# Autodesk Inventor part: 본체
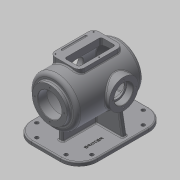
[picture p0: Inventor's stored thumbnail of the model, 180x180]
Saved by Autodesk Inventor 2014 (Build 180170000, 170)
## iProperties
Created: 2016-02
Part Number: 본체
Material: Aluminum 6061
Document SubType Name: Modeling
Designer: mduedu
Density: 2.71 g/cm^3
Appearance: Aluminum - Flat
Author: mduedu
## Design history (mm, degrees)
sketch "스케치2"
  geometry: L1 (0, 100)-(0, -100); L2 (65, -75.993)-(65, 100); L3 (65, 100)-(0, 100); A1 r 100 centre (0, 0) between (0, -100) and (65, -75.993); 2 further points
  constraints: 6 end point, 2 midpoint, 2 point on circle, 1 centre point, 1 coincident, 1 horizontal, 1 parallel, 1 vertical
  dimensions: "d3" = 200 distance of L1.start L1.end; "d5" = 130 diameter of L2 L1; "d6" = 100 radius of A1
revolve "회전1" sketch "스케치2" stored, may be unused: angle "d7" = 90 deg
sketch "스케치3"
  geometry: C1 r 47.5 at (0, 0); 1 further point
  constraints: 1 centre point, 1 coincident
  dimensions: "d8" = 95 diameter of C1
extrude "돌출2" join sketch "스케치3" distance "d10" = 10; taper "d11" = 0 deg
sketch "스케치5"
  geometry: L1 (47.5, 110)-(47.5, 100) reference; L2 (47.5, 100)-(65, 100) reference; L3 (65, 100)-(65, -75.993) reference; L4 (-65, -75.993)-(-65, 100) reference; L5 (-65, 100)-(-47.5, 100) reference; L6 (-47.5, 100)-(-47.5, 110) reference; L7 (-47.5, 110)-(47.5, 110) reference; L8 (55, 85)-(55, -71.239); L9 (0, 85)-(55, 85); L10 (0, 85)-(0, -90); A1 r 100 centre (0, 0) between (0, -100) and (65, -75.993) reference; A2 r 100 centre (0, 0) between (-65, -75.993) and (0, -100) reference; A3 r 90 centre (0, 0) between (0, -90) and (55, -71.239); 1 further point
  constraints: 6 end point, 2 point on circle, 1 centre point, 1 parallel, 1 perpendicular, 1 point on line, 1 vertical
  dimensions: "d13" = 10 distance between parallel lines of L3 L8; "d14" = 10 radial gap between concentric circles of A3 A1; "d15" = 15 distance between parallel lines of L9 L2
revolve "회전2" sketch "스케치5" stored, may be unused: angle "d16" = 90 deg
hole "구멍1" diameter "d19" = 65; stored, may be unused: countersink angle "d23" = 90 deg, drill point angle "d25" = 118 deg; dims "d17" = 10, "d18" = 10, "d20" = 6, "d21" = 4, "d22" = 2, "d24" = 8
node "작업 평면1"
sketch "스케치6"
  geometry: L1 (47.5, 110)-(-47.5, 110) reference; C1 r 40 at (0, -17); 1 further point
  constraints: 1 centre point, 1 vertical alignment
  dimensions: "d27" = 80 diameter of C1; "d29" = 127 distance from line of C1.centre L1
extrude "돌출3" join sketch "스케치6" stored distance "d30" = 10; taper "d31" = 0 deg
hole "구멍2" diameter "d34" = 42; stored, may be unused: countersink angle "d38" = 90 deg, drill point angle "d40" = 118 deg; dims "d32" = 10, "d33" = 10, "d35" = 6, "d36" = 52, "d37" = 18, "d39" = 8
sketch "스케치7" dims "d41" = 65
  geometry: C1 r 40 at (0, 0) reference; 3 further points
  constraints: 2 vertical alignment, 1 coincident, 2 other
hole "구멍3" sketch "스케치7" at (0, 32.5) diameter "d43" = 3.242; stored, may be unused: countersink angle "d47" = 90 deg, drill point angle "d49" = 118 deg; dims "d44" = 11, "d45" = 13, "d46" = 18, "d48" = 13
sketch "스케치8" dims "d53" = 80
  geometry: 3 further points
  constraints: 2 vertical alignment, 1 coincident, 2 other
hole "구멍4" sketch "스케치8" at (0, 40) diameter "d56" = 3.242; stored, may be unused: countersink angle "d60" = 90 deg, drill point angle "d62" = 118 deg; dims "d57" = 11, "d58" = 13, "d59" = 18, "d61" = 13
fillet "모깎기1" dims "d66" = 10
fillet "모깎기2" dims "d67" = 3
fillet "모깎기3" dims "d68" = 0.3
chamfer "모따기1" distance "d69" = 1; stored, may be unused: second distance "d70" = 2, angle "d71" = 45 deg
node "작업 평면5"
sketch "스케치23"
  geometry: L1 (6, 80)-(-6, 80); L2 (-6, 80)-(-6, -60); L3 (-6, -60)-(6, -60); L4 (6, -60)-(6, 80); L5 (-55, 100)-(55, 100) reference; 2 further points
  constraints: 8 end point, 2 parallel, 1 horizontal, 1 midpoint, 1 perpendicular, 1 vertical alignment
  dimensions: "d177" = 12 distance of L1.start L1.end; "d179" = 140 distance of L3.end L1.start; "d180" = 20 distance between parallel lines of L1 L5
extrude "돌출14" join sketch "스케치23" stored distance "d181" = 10; taper "d182" = 0 deg
node "작업 평면6"
sketch "스케치15"
  geometry: L1 (-30, 60)-(50, 60); L2 (50, 60)-(50, -60); L3 (50, -60)-(-30, -60); L4 (-30, -60)-(-30, 60); 3 further points
  constraints: 8 end point, 2 parallel, 1 horizontal, 1 horizontal alignment, 1 midpoint, 1 perpendicular, 1 vertical alignment
  dimensions: "d110" = 80 distance of L2.end L3.end; "d112" = 60 distance from line of L3 point (10, 0); "d113" = 120 distance of L1.end L2.end; "d149" = 30 distance from line of L4 point (0, 0)
extrude "돌출8" join sketch "스케치15" stored distance "d114" = 10; taper "d115" = 0 deg
fillet "모깎기7" dims "d116" = 15
sketch "스케치16"
  geometry: L1 (-30, -45)-(-30, 45) reference; L2 (-15, 60)-(35, 60) reference; L3 (35, -60)-(-15, -60) reference; L4 (-20, -45)-(-20, 45); L5 (-15, 50)-(15, 50); L6 (20, 45)-(20, -45); L7 (15, -50)-(-15, -50); L8 (50, 45)-(50, -45) reference; A1 r 15 centre (-15, -45) between (-30, -45) and (-15, -60) reference; A2 r 15 centre (-15, 45) between (-15, 60) and (-30, 45) reference; A3 r 5 centre (-15, -45) between (-20, -45) and (-15, -50); A4 r 5 centre (-15, 45) between (-15, 50) and (-20, 45); A5 r 5 centre (15, 45) between (20, 45) and (15, 50); A6 r 5 centre (15, -45) between (15, -50) and (20, -45); A7 r 15 centre (35, 45) between (50, 45) and (35, 60) reference; A8 r 15 centre (35, -45) between (35, -60) and (50, -45) reference
  constraints: 8 end point, 8 point on circle, 4 centre point, 2 equal radius, 3 other
  dimensions: "d137" = 10 distance between parallel lines of L4 L1; "d150" = 40 distance between parallel lines of L6 L4; "d151" = 100 distance between parallel lines of L7 L5
extrude "돌출9" cut sketch "스케치16" stored distance "d118" = 10; taper "d119" = 0 deg
fillet "모깎기8" dims "d120" = 3
sketch "스케치17"
  geometry: L1 (-30, -45)-(-30, 45) reference; L2 (-20, 45)-(-20, -45) reference; L3 (-15, -50)-(15, -50) reference; L4 (20, -45)-(20, 45) reference; L5 (15, 50)-(-15, 50) reference; L6 (-15, 60)-(35, 60) reference; L7 (35, -60)-(-15, -60) reference; L8 (15, 55)-(-15, 55); L9 (-25, 45)-(-25, -45); L10 (-15, -55)-(15, -55); L11 (25, -45)-(25, 45); L12 (50, 45)-(50, -45) reference; L13 (35, 55)-(-15, 55); L14 (-25, 45)-(-25, -45); L15 (-15, -55)-(35, -55); L16 (45, -45)-(45, 45); A1 r 5 centre (-15, 45) between (-15, 50) and (-20, 45) reference; A2 r 5 centre (-15, -45) between (-20, -45) and (-15, -50) reference; A3 r 5 centre (15, -45) between (15, -50) and (20, -45) reference; A4 r 5 centre (15, 45) between (20, 45) and (15, 50) reference; A5 r 15 centre (-15, 45) between (-15, 60) and (-30, 45) reference; A6 r 15 centre (-15, -45) between (-30, -45) and (-15, -60) reference; A7 r 10 centre (-15, 45) between (-15, 55) and (-25, 45); A8 r 10 centre (-15, -45) between (-25, -45) and (-15, -55); A9 r 10 centre (15, -45) between (15, -55) and (25, -45); A10 r 10 centre (15, 45) between (25, 45) and (15, 55); A11 r 15 centre (35, 45) between (50, 45) and (35, 60) reference; A12 r 15 centre (35, -45) between (35, -60) and (50, -45) reference; A13 r 10 centre (-15, 45) between (-15, 55) and (-25, 45); A14 r 10 centre (-15, -45) between (-25, -45) and (-15, -55); A15 r 10 centre (35, -45) between (35, -55) and (45, -45); A16 r 10 centre (35, 45) between (45, 45) and (35, 55); 6 further points
  constraints: 18 point on circle, 16 end point, 8 centre point, 4 midpoint, 4 tangent, 11 other
  dimensions: "d138" = 5 distance between parallel lines of L8 L6; "d157" = 5 distance between parallel lines of L12 L16
hole "구멍5" sketch "스케치17" at (-25, 0), (42.071, 52.071), (42.071, -52.071) diameter "d122" = 3.242; stored, may be unused: countersink angle "d126" = 90 deg, drill point angle "d128" = 118 deg; dims "d123" = 9, "d124" = 13, "d125" = 18, "d127" = 11
sketch "스케치19"
  geometry: L1 (-50, 70)-(-35, 70) reference; L2 (-50, 42.603)-(-50, 70) reference; C1 r 2.5 at (-43, 70); 1 further point
  constraints: 1 centre point, 1 point on line
  dimensions: "d152" = 5 diameter of C1; "d153" = 7 distance from line of C1.centre L2
extrude "돌출11" cut sketch "스케치19" stored distance "d154" = 70; taper "d155" = 0 deg
fillet "모깎기11" dims "d156" = 2.5
sketch "스케치20"
  geometry: L1 (-90, 120)-(90, 120); L2 (90, 120)-(90, -120); L3 (90, -120)-(-90, -120); L4 (-90, -120)-(-90, 120); 3 further points
  constraints: 8 end point, 2 parallel, 2 vertical alignment, 1 coincident, 1 horizontal, 1 midpoint, 1 perpendicular
  dimensions: "d162" = 180 distance of L1.start L1.end; "d164" = 240 distance of L1.end L2.end; "d165" = 120 distance from line of L1 point (0, 0)
extrude "돌출12" join sketch "스케치20" distance "d166" = 10; taper "d167" = 0 deg
fillet "모깎기12" dims "d168" = 50
node "작업 평면8"
  node "작업축1"
sketch "스케치24"
  geometry: L1 (128, 34.121)-(127.026, 32.5) reference; L2 (127.026, 32.5)-(128, 30.879) reference; L3 (128, 30.879)-(141, 30.879) reference; L4 (141, 30.879)-(141, 27) reference; L5 (141, 27)-(140, 26) reference; L6 (140, 26)-(123.3, 26) reference; L7 (123, 25.7)-(123, 21) reference; L8 (123, 21)-(116.833, 21) reference; L9 (86, 51.235)-(86, 70) reference; L10 (86, 70)-(106.5, 70) reference; L11 (111.5, 70)-(116, 70) reference; L12 (116, 70)-(116, 42.603) reference; L13 (118.678, 40)-(141, 40) reference; L14 (141, 40)-(141, 34.121) reference; L15 (141, 34.121)-(128, 34.121) reference; L16 (4, -34.121)-(4.974, -32.5) reference; L17 (4.974, -32.5)-(4, -30.879) reference; L18 (4, -30.879)-(-9, -30.879) reference; L19 (-9, -30.879)-(-9, -27) reference; L20 (-9, -27)-(-8, -26) reference; L21 (-8, -26)-(8.7, -26) reference; L22 (9, -25.7)-(9, -21) reference; L23 (9, -21)-(15.167, -21) reference; L24 (116.833, -21)-(123, -21) reference; L25 (123, -21)-(123, -25.7) reference; L26 (123.3, -26)-(140, -26) reference; L27 (140, -26)-(141, -27) reference; L28 (141, -27)-(141, -30.879) reference; L29 (141, -30.879)-(128, -30.879) reference; L30 (128, -30.879)-(127.026, -32.5) reference; L31 (127.026, -32.5)-(128, -34.121) reference; L32 (128, -34.121)-(141, -34.121) reference; L33 (141, -34.121)-(141, -40) reference; L34 (141, -40)-(118.678, -40) reference; L35 (72, -64.722)-(72, -100) reference; L36 (72, -100)-(156, -100) reference; L37 (156, -100)-(156, -110) reference; L38 (156, -110)-(-24, -110) reference; L39 (-24, -110)-(-24, -100) reference; L40 (-24, -100)-(60, -100) reference; L41 (60, -100)-(60, -64.722) reference; L42 (13.322, -40)-(-9, -40) reference; L43 (-9, -40)-(-9, -34.121) reference; L44 (-9, -34.121)-(4, -34.121) reference; L45 (4.974, 32.5)-(4, 34.121) reference; L46 (4, 34.121)-(-9, 34.121) reference; L47 (-9, 34.121)-(-9, 40) reference; L48 (-9, 40)-(13.322, 40) reference; L49 (36, 59.456)-(36, 70) reference; L50 (36, 70)-(46, 70) reference; L51 (46, 70)-(46, 51.235) reference; L52 (15.167, 21)-(9, 21) reference; L53 (9, 21)-(9, 25.7) reference; L54 (8.7, 26)-(-8, 26) reference; L55 (-8, 26)-(-9, 27) reference; L56 (-9, 27)-(-9, 30.879) reference; L57 (-9, 30.879)-(4, 30.879) reference; L58 (4, 30.879)-(4.974, 32.5) reference; L59 (-1, -40)-(-11.58, -100); A1 r 0.3 centre (123.3, 25.7) between (123.3, 26) and (123, 25.7) reference; A2 r 55 centre (66, 0) between (116.833, 21) and (86, 51.235) reference; A3 r 2.5 centre (109, 70) between (106.5, 70) and (111.5, 70) reference; A4 r 3 centre (119, 42.603) between (116, 42.603) and (116.516, 40.92) reference; A5 r 0.3 centre (8.7, -25.7) between (8.7, -26) and (9, -25.7) reference; A6 r 55 centre (66, 0) between (15.167, -21) and (116.833, -21) reference; A7 r 0.3 centre (123.3, -25.7) between (123, -25.7) and (123.3, -26) reference; A8 r 65 centre (66, 0) between (72, -64.722) and (116.354, -41.103) reference; A9 r 65 centre (66, 0) between (15.646, -41.103) and (60, -64.722) reference; A10 r 65 centre (66, 0) between (34.456, 56.833) and (15.646, 41.103) reference; A11 r 3 centre (33, 59.456) between (34.456, 56.833) and (36, 59.456) reference; A12 r 55 centre (66, 0) between (46, 51.235) and (15.167, 21) reference; A13 r 0.3 centre (8.7, 25.7) between (9, 25.7) and (8.7, 26) reference; 1 further point
  constraints: 2 end point, 2 point on line, 4 other
  dimensions: "d184" = 8 distance of L59.start L42.end; "d185" = 100 deg angle of L59 L40
feature "리브2" sketch "스케치24" dims "d186" = 1, "d187" = 12, "d188" = 0, "d189" = 0, "d190" = 1, "d191" = 1
fillet "모깎기15" dims "d192" = 3
fillet "모깎기16" dims "d193" = 3
sketch "스케치25"
  geometry: L1 (90, -70)-(90, 70) reference; L2 (40, 120)-(-40, 120) reference; L3 (-90, 70)-(-90, -70) reference; L4 (-40, -120)-(40, -120) reference; L5 (-74.004, 8)-(-9, 8) reference; L6 (-80.097, 20)-(-80.097, 14) reference; L7 (-9, 26)-(-74.004, 26) reference; L8 (-9, 57)-(-9, 26) reference; L9 (3, 63)-(-3, 63) reference; L10 (9, 26)-(9, 57) reference; L11 (74.004, 26)-(9, 26) reference; L12 (80.097, 14)-(80.097, 20) reference; L13 (9, 8)-(74.004, 8) reference; L14 (9, -77)-(9, 8) reference; L15 (-3, -83)-(3, -83) reference; L16 (-9, 8)-(-9, -77) reference; L17 (-40, 105)-(40, 105); L18 (75, 70)-(75, -70); L19 (40, -105)-(-40, -105); L20 (-75, -70)-(-75, 70); C1 r 5 at (-75, 70); C2 r 5 at (-40, 105); C3 r 5 at (40, 105); C4 r 5 at (75, 70); C5 r 5 at (75, -70); C6 r 5 at (40, -105); C7 r 5 at (-40, -105); C8 r 5 at (-75, -70); A1 r 50 centre (40, 70) between (90, 70) and (40, 120) reference; A2 r 50 centre (-40, 70) between (-40, 120) and (-90, 70) reference; A3 r 50 centre (-40, -70) between (-90, -70) and (-40, -120) reference; A4 r 50 centre (40, -70) between (40, -120) and (90, -70) reference; A5 r 6 centre (-3, 57) between (-3, 63) and (-9, 57) reference; A6 r 6 centre (3, 57) between (9, 57) and (3, 63) reference; A7 r 6 centre (3, -77) between (3, -83) and (9, -77) reference; A8 r 6 centre (-3, -77) between (-9, -77) and (-3, -83) reference; A9 r 35 centre (40, 70) between (75, 70) and (40, 105); A10 r 35 centre (40, -70) between (40, -105) and (75, -70); A11 r 35 centre (-40, -70) between (-75, -70) and (-40, -105); A12 r 35 centre (-40, 70) between (-40, 105) and (-75, 70); 5 further points; 4 other entities
  constraints: 12 centre point, 8 coincident, 8 end point, 8 point on circle, 7 equal radius, 11 other
  dimensions: "d194" = 15 distance between parallel lines of L17 L2; "d195" = 10 diameter of C1
extrude "돌출15" cut sketch "스케치25" stored distance "d197" = 10; taper "d198" = 0 deg
fillet "모깎기14" dims "d170" = 3
sketch "스케치22"
  geometry: L1 (90, -70)-(90, 70) reference; 2 further points
  constraints: 1 other
  dimensions: "d174" = 40 distance from line of L1 point (50, -40); "d199" = 40 vertical distance of point (50, -40) point (0, 0)
feature "엠보싱2" sketch "스케치22" dims "d13" = 10, "d175" = 0.5, "d176" = 0
node "솔리드2"
pattern_circular "원형 패턴1" dims angle "d51" = 360 deg
mirror "대칭1"
pattern_circular "원형 패턴2" dims angle "d64" = 360 deg
mirror "대칭3"
node "투영된 루프2"
node "절단 모서리 투영1"
node "절단 모서리 투영2"
node "절단 모서리 투영3"
node "절단 모서리 투영4"
other parameters: "d26" = 75, "d183" = 0
